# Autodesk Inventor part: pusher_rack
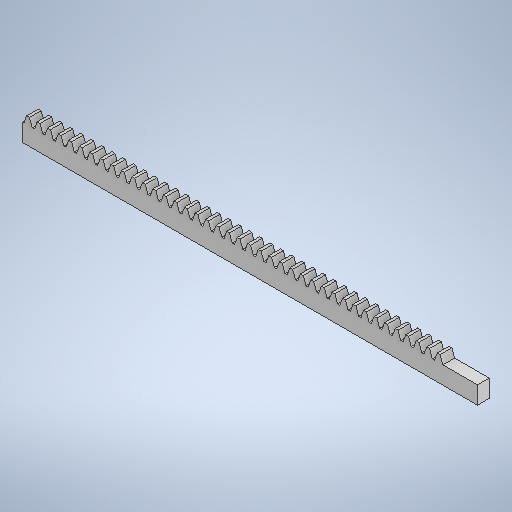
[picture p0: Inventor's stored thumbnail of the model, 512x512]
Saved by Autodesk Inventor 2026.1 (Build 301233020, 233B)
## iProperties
Company: meta-matic.com
Created: 2026-10
Part Number: pusher_rack
Material: Generic
Description: Rack Gear - meta-matic-generator 1.3
Document SubType Name: Modeling
Designer: alolo
Authority: META-MATIC-ID: 956ca585bc87
Density: 1 g/cm^3
Appearance: Default
Sending System: Open CASCADE
Preprocessor: meta-matic-generator 1.3
Title: Rack Gear_956ca585bc87
Author: Takahashi Mizuki @tkhsmz
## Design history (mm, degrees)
feature "Base1"
sketch "Sketch1"
  geometry: L1 (0, 10.5)-(0, 0) reference; L2 (10, 0)-(0, 0); L3 (0, 0)-(0, 10.5); L4 (0, 10.5)-(10, 10.5); L5 (10, 10.5)-(10, 0); 1 further point
  constraints: 8 end point, 2 parallel, 1 horizontal, 1 perpendicular
extrude "Extrusion1" join sketch "Sketch1" distance "d0" = 20; taper "d1" = 0 deg
sketch "Sketch3"
  geometry: L1 (0, 0)-(0, 10.5) reference; L2 (0, 0)-(271.327, 0) reference; L3 (271.327, 10.5)-(271.327, 0) reference; L4 (250.667, 10.5)-(271.327, 10.5) reference; L5 (249.029, 15)-(250.667, 10.5) reference; L6 (247.343, 15)-(249.029, 15) reference; L7 (245.705, 10.5)-(247.343, 15) reference; L8 (244.383, 10.5)-(245.705, 10.5) reference; L9 (242.745, 15)-(244.383, 10.5) reference; L10 (241.06, 15)-(242.745, 15) reference; L11 (239.422, 10.5)-(241.06, 15) reference; L12 (238.1, 10.5)-(239.422, 10.5) reference; L13 (236.462, 15)-(238.1, 10.5) reference; L14 (234.777, 15)-(236.462, 15) reference; L15 (233.139, 10.5)-(234.777, 15) reference; L16 (231.817, 10.5)-(233.139, 10.5) reference; L17 (230.179, 15)-(231.817, 10.5) reference; L18 (228.493, 15)-(230.179, 15) reference; L19 (226.856, 10.5)-(228.493, 15) reference; L20 (225.534, 10.5)-(226.856, 10.5) reference; L21 (223.896, 15)-(225.534, 10.5) reference; L22 (222.21, 15)-(223.896, 15) reference; L23 (220.572, 10.5)-(222.21, 15) reference; L24 (219.251, 10.5)-(220.572, 10.5) reference; L25 (217.613, 15)-(219.251, 10.5) reference; L26 (215.927, 15)-(217.613, 15) reference; L27 (214.289, 10.5)-(215.927, 15) reference; L28 (212.967, 10.5)-(214.289, 10.5) reference; L29 (211.33, 15)-(212.967, 10.5) reference; L30 (209.644, 15)-(211.33, 15) reference; L31 (208.006, 10.5)-(209.644, 15) reference; L32 (206.684, 10.5)-(208.006, 10.5) reference; L33 (205.046, 15)-(206.684, 10.5) reference; L34 (203.361, 15)-(205.046, 15) reference; L35 (201.723, 10.5)-(203.361, 15) reference; L36 (200.401, 10.5)-(201.723, 10.5) reference; L37 (198.763, 15)-(200.401, 10.5) reference; L38 (197.077, 15)-(198.763, 15) reference; L39 (195.44, 10.5)-(197.077, 15) reference; L40 (194.118, 10.5)-(195.44, 10.5) reference; L41 (192.48, 15)-(194.118, 10.5) reference; L42 (190.794, 15)-(192.48, 15) reference; L43 (189.156, 10.5)-(190.794, 15) reference; L44 (187.835, 10.5)-(189.156, 10.5) reference; L45 (186.197, 15)-(187.835, 10.5) reference; L46 (184.511, 15)-(186.197, 15) reference; L47 (182.873, 10.5)-(184.511, 15) reference; L48 (181.552, 10.5)-(182.873, 10.5) reference; L49 (179.914, 15)-(181.552, 10.5) reference; L50 (178.228, 15)-(179.914, 15) reference; L51 (176.59, 10.5)-(178.228, 15) reference; L52 (175.268, 10.5)-(176.59, 10.5) reference; L53 (173.63, 15)-(175.268, 10.5) reference; L54 (171.945, 15)-(173.63, 15) reference; L55 (170.307, 10.5)-(171.945, 15) reference; L56 (168.985, 10.5)-(170.307, 10.5) reference; L57 (167.347, 15)-(168.985, 10.5) reference; L58 (165.662, 15)-(167.347, 15) reference; L59 (164.024, 10.5)-(165.662, 15) reference; L60 (162.702, 10.5)-(164.024, 10.5) reference; L61 (161.064, 15)-(162.702, 10.5) reference; L62 (159.378, 15)-(161.064, 15) reference; L63 (157.741, 10.5)-(159.378, 15) reference; L64 (156.419, 10.5)-(157.741, 10.5) reference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; 1 further point
extrude "Extrusion2" cut sketch "Sketch3" distance "d2" = 3; taper "d3" = 0 deg
body "Solid1"
node "Projected Loop1"
